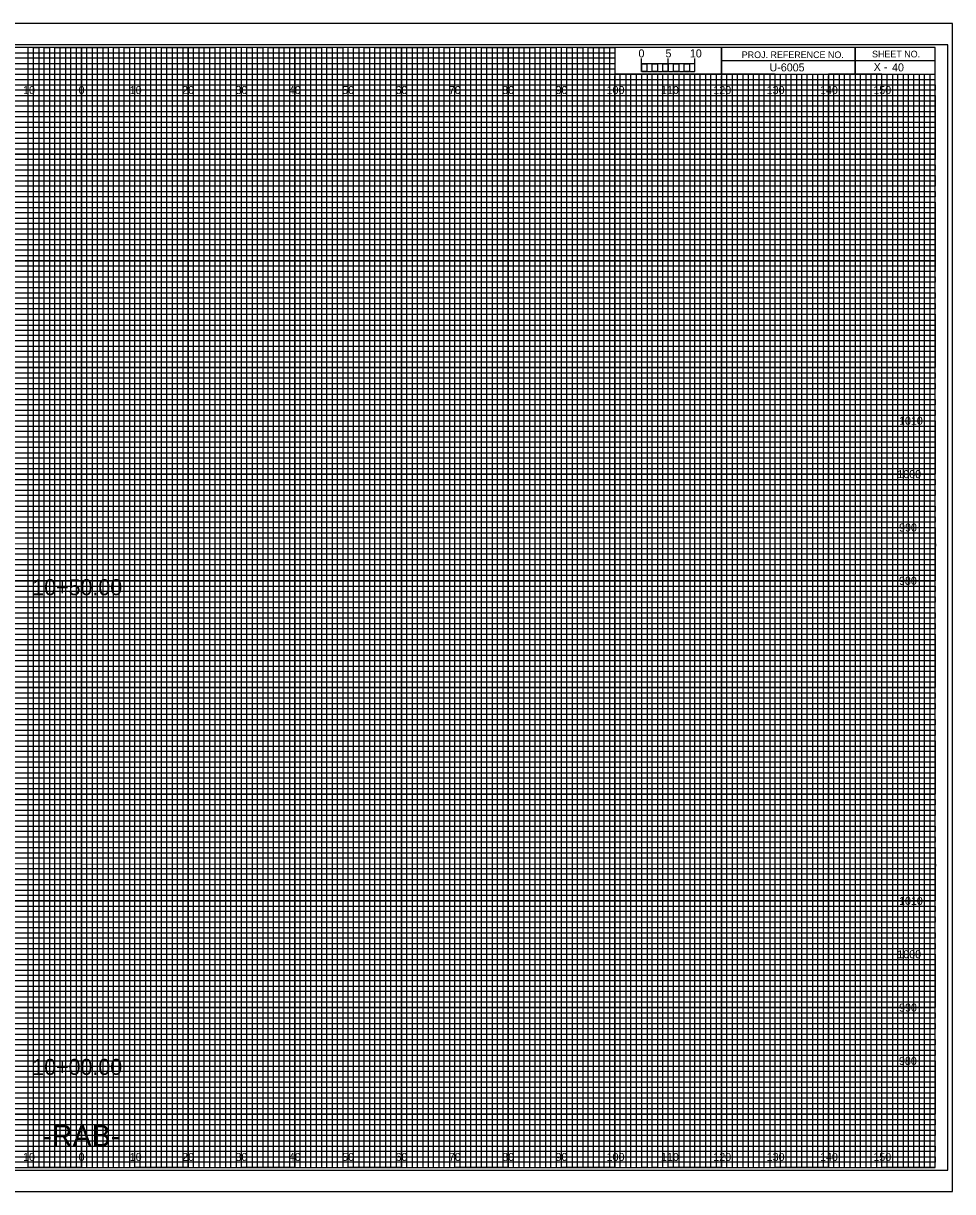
# Model space of a CAD drawing. Extents: x -13 to 323, y -5 to 215.
# Drawn here: x 149.1 to 323.3, y -4.5 to 214.5 of the extents above; entities that cross this region are included whole.
import ezdxf

# ---------------------------------------------------------------- set-up
doc = ezdxf.new("R2010")
doc.units = 0
for name, color, linetype in [('Exist Cross Section Cell', 7, 'Continuous'), ('Exist XS Center Line Elevation Label', 7, 'Continuous'), ('Exist XS Ground Line', 7, 'Continuous'), ('Prop XS Dump Level', 7, 'Continuous'), ('Prop XS EOT Tick Mark', 7, 'Continuous'), ('Prop XS Finish Grade', 7, 'Continuous'), ('Prop XS Finish Grade CurbGutter', 7, 'Continuous'), ('Prop XS Finish Grade Earthwork', 7, 'Continuous'), ('Prop XS Finish Grade Pavement', 7, 'Continuous'), ('Prop XS Hydro Elevations', 7, 'Continuous'), ('Prop XS Pvmt Edge Slope', 7, 'Continuous'), ('Prop XS SE Text', 7, 'Continuous'), ('Prop XS Side Slope Text', 7, 'Continuous'), ('Prop XS SS Elevation Text', 7, 'Continuous'), ('Prop XS Subgrade CurbGutter', 7, 'Continuous'), ('Prop XS Subgrade Earthwork', 7, 'Continuous'), ('Scratch_Level_0', 7, 'Continuous')]:
    doc.layers.add(name, color=color, linetype=linetype)

msp = doc.modelspace()

# ---------------------------------------------------------------- linework, layer by layer
at = {"layer": 'Exist XS Center Line Elevation Label'}
for points in [[(145, 0), (155, 0), (155, 210), (165, 210), (165, 0), (175, 0), (175, 210), (185, 210), (185, 0), (195, 0), (195, 210), (205, 210), (205, 0), (215, 0), (215, 210), (225, 210), (225, 0), (235, 0), (235, 210), (245, 210), (245, 0), (255, 0), (255, 210), (259.93, 210), (260, 210), (260, 205), (264.99, 205), (264.99, 0), (275, 0), (275, 205), (285, 205), (285, 0), (295, 0), (295, 205), (305, 205), (305, 0), (315, 0), (315, 205)], [(0, 205), (275, 205)], [(0, 185), (320, 185), (320, 195), (0, 195)], [(0, 165), (320, 165), (320, 175), (0, 175)], [(0, 145), (320, 145), (320, 155), (0, 155)], [(0, 125), (320, 125), (320, 135), (0, 135)], [(0, 105), (320, 105), (320, 115), (0, 115)], [(0, 85), (320, 85), (320, 95), (0, 95)], [(0, 65), (320, 65), (320, 75), (0, 75)], [(0, 45), (320, 45), (320, 55), (0, 55)], [(0, 25), (320, 25), (320, 35), (0, 35)], [(0, 5), (320, 5), (320, 15), (0, 15)]]:
    msp.add_lwpolyline(points, dxfattribs=at)
at = {"layer": 'Exist XS Ground Line'}
for p, q in [((150, 210), (140, 210)), ((150, 0), (150, 210)), ((170, 210), (160, 210)), ((160, 210), (160, 0)), ((170, 0), (170, 210)), ((190, 210), (180, 210)), ((180, 210), (180, 0)), ((190, 0), (190, 210)), ((210, 210), (200, 210)), ((200, 210), (200, 0)), ((210, 0), (210, 210)), ((230, 210), (220, 210)), ((220, 210), (220, 0)), ((230, 0), (230, 210)), ((250, 210), (240, 210)), ((240, 210), (240, 0)), ((250, 0), (250, 210)), ((260, 210), (260, 0)), ((270, 0), (270, 205)), ((290, 205), (280, 205)), ((280, 205), (280, 0)), ((290, 0), (290, 205)), ((310, 205), (300, 205)), ((300, 205), (300, 0)), ((310, 0), (310, 205)), ((160, 0), (150, 0)), ((180, 0), (170, 0)), ((200, 0), (190, 0)), ((220, 0), (210, 0)), ((240, 0), (230, 0)), ((260, 0), (250, 0)), ((280, 0), (270, 0)), ((300, 0), (290, 0)), ((320, 0), (310, 0)), ((320, 0), (320, 0))]:
    msp.add_line(p, q, dxfattribs=at)
for points in [[(0, 200), (320, 200), (320, 190), (0, 190)], [(0, 180), (320, 180), (320, 170), (0, 170)], [(0, 160), (320, 160), (320, 150), (0, 150)], [(0, 140), (320, 140), (320, 130), (0, 130)], [(0, 120), (320, 120), (320, 110), (0, 110)], [(0, 100), (320, 100), (320, 90), (0, 90)], [(0, 80), (320, 80), (320, 70), (0, 70)], [(0, 60), (320, 60), (320, 50), (0, 50)], [(0, 40), (320, 40), (320, 30), (0, 30)], [(0, 20), (320, 20), (320, 10), (0, 10)]]:
    msp.add_lwpolyline(points, dxfattribs=at)
at = {"layer": 'Prop XS Dump Level'}
for p, q in [((0, 209), (260, 209)), ((260, 209), (260, 207.98)), ((260, 207.98), (0, 207.98)), ((0, 207), (260, 207)), ((260, 205.89), (0, 205.89)), ((260, 207), (260, 205.89)), ((0, 204), (320, 204))]:
    msp.add_line(p, q, dxfattribs=at)
for points in [[(0, 203), (270, 203), (320, 203), (320, 202), (0, 202)], [(0, 201), (320, 201), (320, 199), (0, 199)], [(0, 198), (320, 198), (320, 197), (0, 196.98)], [(0, 196), (320, 196), (320, 194), (0, 194)], [(0, 193), (320, 193), (320, 192), (0, 192)], [(0, 191), (320, 191), (320, 189), (0, 189)], [(0, 188), (320, 188), (320, 187), (0, 187)], [(0, 186), (320, 186), (320, 184), (0, 184)], [(0, 183), (320, 183), (320, 182), (0, 182)], [(0, 181), (320, 181), (320, 179), (0, 179)], [(0, 178), (320, 178), (320, 177), (0, 177)], [(0, 176), (320, 176), (320, 173.95), (320, 173), (320, 172), (0, 172)], [(0, 174), (320, 174), (320, 173), (0, 173)], [(0, 171), (320, 171), (320, 169), (0, 169.03)], [(0, 169.03), (320, 169), (320, 168), (0, 168)], [(0, 167), (320, 167), (320, 166), (0, 166)], [(0, 164), (320, 164), (320, 163), (0, 163)], [(0, 162), (320, 162), (320, 161), (0, 161)], [(-0.07, 158.89), (320, 158.89), (320, 157.88), (-0.07, 157.88)], [(0, 157), (320, 157), (320, 156), (0, 156)], [(0, 154), (320, 154), (320, 153), (0, 153)], [(0, 152), (320, 152), (320, 151), (0, 151)], [(0, 149), (320, 149), (320, 148), (0, 148)], [(0, 147), (320, 147), (320, 146), (0, 146)], [(0, 144), (320, 144), (320, 143), (0, 143)], [(0, 142), (320, 142), (320, 141), (0, 141)], [(0, 139), (320, 139), (319.99, 137.98), (0, 138)], [(0, 137), (320, 137), (320, 136), (0, 136)], [(0, 134), (320, 134), (320, 133), (0, 133)], [(0, 132), (320, 132), (320, 131), (0, 131)], [(0, 129), (320, 129), (320, 128), (0, 128)], [(0, 127), (320, 127), (320, 126), (0, 126)], [(0, 124), (320, 124), (320, 123), (0, 123)], [(0, 122), (320, 122), (320, 121), (0, 121)], [(0, 119), (320, 119), (320, 118), (0, 118)], [(0, 116.99), (320.07, 116.91), (320, 116), (0, 116)], [(0, 114), (320, 114), (320, 113), (0, 113)], [(0, 112), (320, 112), (320, 111), (0, 111)], [(0, 109), (320, 109), (320, 108), (0, 108)], [(0, 107), (320, 107), (320, 106), (0, 106)], [(0, 104), (320, 104), (320, 103), (0, 103)], [(0, 102), (320, 102), (320, 101), (0, 101)], [(0, 99), (320, 99), (320, 98), (0, 98)], [(0, 97), (320, 97), (320, 96), (0, 96)], [(0, 94), (320, 94), (320, 93), (0, 93)], [(0, 92), (320, 92), (320, 91), (0, 91)], [(0, 89), (320, 89), (320, 88), (0, 88)], [(0, 87), (320, 87), (320, 86), (0, 86)], [(0, 84), (320, 84), (320, 83), (0, 83)], [(0, 82), (320, 82), (320, 81), (0, 81)], [(0, 79), (320, 79), (319.99, 77.98), (0, 78)], [(0, 77), (320, 77), (320, 76), (0, 76)], [(0, 74), (320, 74), (320, 73), (0, 73)], [(0, 72), (320, 72), (320, 71), (0, 71)], [(0, 69), (320, 69), (320, 68), (0, 68)], [(0, 67), (320, 67), (320, 66), (0, 66)], [(0, 64), (320, 64), (320, 63), (0, 63)], [(0, 62), (320, 62), (320, 61), (0, 61)], [(0, 59), (320, 59), (320, 58), (0, 58)], [(0, 56.99), (320.07, 56.91), (320, 56), (0, 56)], [(0, 54), (320, 54), (320, 53), (0, 53)], [(0, 52), (320, 52), (320, 51), (0, 51)], [(0, 49), (320, 49), (320, 48), (0, 48)], [(0, 47), (320, 47), (320, 46), (0, 46)], [(0, 44), (320, 44), (320, 43), (0, 43)], [(0, 42), (320, 42), (320, 41), (0, 41)], [(0, 39), (320, 39), (320, 38), (0, 38)], [(0, 37), (320, 37), (320, 36), (0, 36)], [(0, 34), (320, 34), (320, 33), (0, 33)], [(0, 32), (320, 32), (320, 31), (0, 31)], [(0, 29), (320, 29), (320, 28), (0, 28)], [(0, 27), (320, 27), (320, 26), (0, 26)], [(0, 24), (320, 24), (320, 23), (0, 23)], [(0, 22), (320, 22), (320, 21), (0, 21)], [(0, 19), (320, 19), (320, 18), (0, 18)], [(0, 17), (320, 17), (320, 16), (0, 16)], [(0, 14), (320, 14), (320, 13), (0, 13)], [(0, 12), (320, 12), (320, 11), (0, 11)], [(0, 9), (320, 9), (320, 8), (0, 8)], [(0, 7), (320, 7), (320, 6), (0, 6)], [(0, 4), (320, 4), (320, 3), (0, 3)], [(0, 2), (320, 2), (320, 1), (0, 1)]]:
    msp.add_lwpolyline(points, dxfattribs=at)
at = {"layer": 'Prop XS Finish Grade'}
for p, q in [((150, 0), (150, 210)), ((160, 0), (160, 210)), ((170, 0), (170, 210)), ((180, 0), (180, 210)), ((190, 0), (190, 210)), ((200, 0), (200, 210)), ((210, 0), (210, 210)), ((220, 0), (220, 210)), ((230, 0), (230, 210)), ((240, 0), (240, 210)), ((250, 0), (250, 210)), ((260, 0), (260, 204.69)), ((270, 0), (270, 204.69)), ((280, 0), (280, 204.69)), ((290, 0), (290, 204.69)), ((300, 0), (300, 204.69)), ((310, 0), (310, 204.69)), ((0, 200), (320, 200)), ((0, 190), (320, 190)), ((0, 180), (320, 180)), ((0, 170), (320, 170)), ((0, 160), (320, 160)), ((0, 150), (320, 150)), ((0, 140), (320, 140)), ((0, 130), (320, 130)), ((0, 120), (320, 120)), ((0, 110), (320, 110)), ((0, 100), (320, 100)), ((0, 90), (320, 90)), ((0, 80), (320, 80)), ((0, 70), (320, 70)), ((0, 60), (320, 60)), ((0, 50), (320, 50)), ((0, 40), (320, 40)), ((0, 30), (320, 30)), ((0, 20), (320, 20)), ((0, 10), (320, 10))]:
    msp.add_line(p, q, dxfattribs=at)
at = {"layer": 'Prop XS Finish Grade Earthwork'}
msp.add_lwpolyline([(-13.4, -4.5), (323.3, -4.5), (323.3, 214.5), (-13.4, 214.5)], close=True, dxfattribs=at)
at = {"layer": 'Prop XS Hydro Elevations'}
for p, q in [((305, 210), (305, 205)), ((305, 205), (305, 210)), ((280, 207.5), (280, 205)), ((320, 207.49), (280, 207.49)), ((280, 205), (320, 205))]:
    msp.add_line(p, q, dxfattribs=at)
for points in [[(320, 210), (0, 210), (0, 0), (320, 0)], [(280, 210), (260, 210), (260, 205.03), (280, 205.03)], [(320, 210), (280, 210), (280, 205), (320, 205)]]:
    msp.add_lwpolyline(points, close=True, dxfattribs=at)
at = {"layer": 'Prop XS Pvmt Edge Slope'}
msp.add_lwpolyline([(-10.8, -0.5), (322.4, -0.5), (322.4, 210.5), (-10.8, 210.5)], close=True, dxfattribs=at)
at = {"layer": 'Prop XS Side Slope Text'}
for p, q in [((265, 205.49), (265, 207.9)), ((265, 206.9), (265, 207.9)), ((270, 205.49), (270, 207.9)), ((275, 205.49), (275, 207.9)), ((275, 206.9), (275, 207.9))]:
    msp.add_line(p, q, dxfattribs=at)
for points in [[(275, 206.9), (265, 206.9), (265, 205.49), (275, 205.49)], [(265, 206.9), (266, 206.9), (266, 205.49), (265, 205.49)], [(267, 206.9), (268, 206.9), (268, 205.49), (267, 205.49)], [(269, 206.9), (270, 206.9), (270, 205.49), (269, 205.49)], [(271, 206.9), (272, 206.9), (272, 205.49), (271, 205.49)], [(273, 206.9), (274, 206.9), (274, 205.49), (273, 205.49)]]:
    msp.add_lwpolyline(points, close=True, dxfattribs=at)
at = {"layer": 'Prop XS SS Elevation Text'}
for p, q in [((267, 205), (266.01, 205)), ((266.01, 205), (266.01, 0)), ((267, 0), (267, 205)), ((269, 205), (268, 205)), ((268, 205), (268, 0)), ((269, 0), (269, 205)), ((266.01, 0), (265, 0)), ((268, 0), (267, 0))]:
    msp.add_line(p, q, dxfattribs=at)
for points in [[(150, 0), (151, 0), (151, 210), (152, 210), (152, 0)], [(152, 0), (153, 0), (153, 210), (154, 210), (154, 0)], [(155, 0), (156, 0), (156, 210), (157, 210), (157, 0)], [(157, 0), (158, 0), (158, 210), (159, 210), (159, 0)], [(160, 0), (161, 0), (161, 210), (162, 210), (162, 0)], [(162, 0), (163, 0), (163, 210), (164, 210), (164, 0)], [(165, 0), (166, 0), (166, 210), (167, 210), (167, 0)], [(167, 0), (168, 0), (168, 210), (169, 210), (169, 0)], [(170, 0), (171, 0), (171, 210), (172, 210), (172, 0)], [(172, 0), (173, 0), (173, 210), (174, 210), (174, 0)], [(175, 0), (176, 0), (176, 210), (177, 210), (177, 0)], [(177, 0), (178, 0), (178, 210), (179, 210), (179, 0)], [(180, 0), (181, 0), (181, 210), (182, 210), (182, 0)], [(182, 0), (183, 0), (183, 210), (184, 210), (184, 0)], [(185, 0), (186, 0), (186, 210), (187, 210), (187, 0)], [(187, 0), (188, 0), (188, 210), (189, 210), (189, 0)], [(190, 0), (191, 0), (191, 210), (192, 210), (192, 0)], [(192, 0), (193, 0), (193, 210), (194, 210), (194, 0)], [(195, 0), (196, 0), (196, 210), (197, 210), (197, 0)], [(197, 0), (198, 0), (198, 210), (199, 210), (199, 0)], [(200, 0), (201, 0), (201, 210), (202, 210), (202, 0)], [(202, 0), (203, 0), (203, 210), (204, 210), (204, 0)], [(205, 0), (206, 0), (206, 210), (207, 210), (207, 0)], [(207, 0), (208, 0), (208, 210), (209, 210), (209, 0)], [(210, 0), (211, 0), (211, 210), (212, 210), (212, 0)], [(212, 0), (213, 0), (213, 210), (214, 210), (214, 0)], [(215, 0), (216, 0), (216, 210), (217, 210), (217, 0)], [(217, 0), (218, 0), (218, 210), (219, 210), (219, 0)], [(220, 0), (221, 0), (221, 210), (222, 210), (222, 0)], [(222, 0), (223, 0), (223, 210), (224, 210), (224, 0)], [(225, 0), (226, 0), (226, 210), (227, 210), (227, 0)], [(227, 0), (228, 0), (228, 210), (229, 210), (229, 0)], [(230, 0), (231, 0), (231, 210), (232, 210), (232, 0)], [(232, 0), (233, 0), (233, 210), (234, 210), (234, 0)], [(235, 0), (236, 0), (236, 210), (237, 210), (237, 0)], [(237, 0), (238, 0), (238, 210), (239, 210), (239, 0)], [(240, 0), (241, 0), (241, 210), (242, 210), (242, 0)], [(242, 0), (243, 0), (243, 210), (244, 210), (244, 0)], [(245, 0), (246, 0), (246, 210), (247, 210), (247, 0)], [(247, 0), (248, 0), (248, 210), (249, 210), (249, 0)], [(250, 0), (251, 0), (251, 210), (252, 210), (252, 0)], [(252, 0), (253, 0), (253, 210), (254, 210), (254, 0)], [(255, 0), (256, 0), (256, 210), (257, 210), (257, 0)], [(257, 0), (258, 0), (258, 210), (259, 210), (259, 0)], [(260, 0), (261, 0), (261, 205), (262.02, 205), (262.02, 0)], [(262, 0), (263, 0), (263, 205), (263.99, 205), (263.99, 0)], [(270, 0), (270.98, 0), (270.98, 205), (272, 205), (272, 0)], [(272, 0), (273, 0), (273, 205), (274.05, 205), (274.05, 0)], [(275, 0), (276, 0), (276, 205), (277, 205), (277, 0)], [(277, 0), (278, 0), (278, 205), (279, 205), (279, 0)], [(280, 0), (281, 0), (281, 205), (282, 205), (282, 0)], [(282, 0), (283, 0), (283, 205), (284, 205), (284, 0)], [(285, 0), (286, 0), (286, 205), (287, 205), (287, 0)], [(287, 0), (288, 0), (288, 205), (289, 205), (289, 0)], [(290, 0), (291, 0), (291, 205), (292, 205), (292, 0)], [(292, 0), (293, 0), (293, 205), (294, 205), (294, 0)], [(295, 0), (296, 0), (296, 205), (297, 205), (297, 0)], [(297, 0), (298, 0), (298, 205), (299, 205), (299, 0)], [(300, 0), (301, 0), (301, 205), (302, 205), (302, 0)], [(302, 0), (303, 0), (303, 205), (304, 205), (304, 0)], [(305, 0), (306, 0), (306, 205), (307, 205), (307, 0)], [(307, 0), (308, 0), (308, 205), (309, 205), (309, 0)], [(310, 0), (311, 0), (311, 205), (312, 205), (312, 0)], [(312, 0), (313, 0), (313, 205), (314, 205), (314, 0)], [(315, 0), (316, 0), (316, 205), (317, 205), (317, 0)], [(317, 0), (318, 0), (318, 205), (319, 205), (319, 0)]]:
    msp.add_lwpolyline(points, dxfattribs=at)
at = {"layer": 'Prop XS Subgrade Earthwork'}
for p, q in [((323.3, 214.5), (-13.4, 214.5)), ((-13.4, -4.5), (323.3, -4.5))]:
    msp.add_line(p, q, dxfattribs=at)

# ---------------------------------------------------------------- texts
at = {"layer": 'Exist Cross Section Cell'}
for s, p in [('10', (149.04, 201.25)), ('0', (159.45, 201.25)), ('0', (159.45, 201.25)), ('10', (169.04, 201.25)), ('20', (178.86, 201.25)), ('30', (188.86, 201.25)), ('40', (198.86, 201.25)), ('50', (208.86, 201.25)), ('60', (218.86, 201.25)), ('70', (228.86, 201.25)), ('80', (238.86, 201.25)), ('90', (248.86, 201.25)), ('100', (258.44, 201.25)), ('110', (268.62, 201.25)), ('120', (278.44, 201.25)), ('130', (288.44, 201.25)), ('140', (298.44, 201.25)), ('150', (308.44, 201.25)), ('10', (149.04, 1.25)), ('0', (159.45, 1.25)), ('0', (159.45, 1.25)), ('10', (169.04, 1.25)), ('20', (178.86, 1.25)), ('30', (188.86, 1.25)), ('40', (198.86, 1.25)), ('50', (208.86, 1.25)), ('60', (218.86, 1.25)), ('70', (228.86, 1.25)), ('80', (238.86, 1.25)), ('90', (248.86, 1.25)), ('100', (258.44, 1.25)), ('110', (268.62, 1.25)), ('120', (278.44, 1.25)), ('130', (288.44, 1.25)), ('140', (298.44, 1.25)), ('150', (308.44, 1.25))]:
    msp.add_text(s, height=1.5, dxfattribs=at).set_placement(p)
at = {"layer": 'Prop XS EOT Tick Mark'}
msp.add_text('40', height=1.5, dxfattribs=at).set_placement((311.94, 205.5))
at = {"layer": 'Prop XS Finish Grade CurbGutter'}
for s, p in [('10+50.00', (150.77, 107.3)), ('10+00.00', (150.77, 17.38))]:
    msp.add_text(s, height=3, dxfattribs=at).set_placement(p)
at = {"layer": 'Prop XS Finish Grade Pavement'}
msp.add_text('-RAB-', height=4, dxfattribs=at).set_placement((152.67, 4))
at = {"layer": 'Prop XS Hydro Elevations'}
for s, height, p in [('PROJ. REFERENCE NO.', 1.25, (283.77, 207.99)), ('SHEET NO.', 1.25, (308.19, 208.12)), ('X -    ', 1.5, (308.5, 205.58))]:
    msp.add_text(s, height=height, dxfattribs=at).set_placement(p)
at = {"layer": 'Prop XS SE Text'}
msp.add_text('U-6005', height=1.5, dxfattribs=at).set_placement((288.97, 205.5))
at = {"layer": 'Prop XS Side Slope Text'}
msp.add_text('0', height=1.5, dxfattribs=at).set_placement((264.41, 208.12))
at = {"layer": 'Prop XS Subgrade CurbGutter'}
for s, p in [('1010', (313.25, 139.25)), ('1000', (312.92, 129.25)), ('990', (313.26, 119.25)), ('980', (313.24, 109.25)), ('1010', (313.25, 49.25)), ('1000', (312.92, 39.25)), ('990', (313.26, 29.25)), ('980', (313.24, 19.25))]:
    msp.add_text(s, height=1.5, dxfattribs=at).set_placement(p)
at = {"layer": 'Scratch_Level_0'}
for s, p in [('5', (269.47, 208.12)), ('10', (274.04, 208.12))]:
    msp.add_text(s, height=1.5, dxfattribs=at).set_placement(p)

doc.saveas('drawing.dxf')
